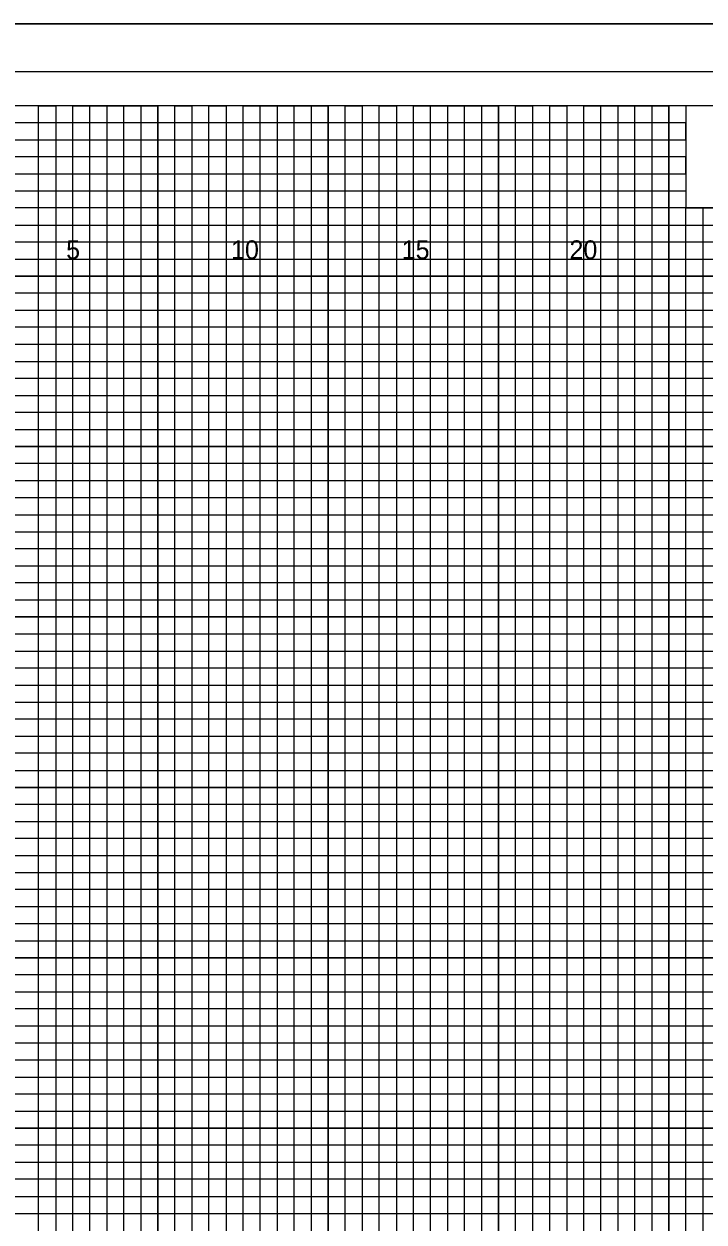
# Model space of a CAD drawing. Extents: x -4 to 103, y -2 to 209.
# Drawn here: x 54.82 to 74.78, y 103.07 to 138.22 of the extents above; entities that cross this region are included whole.
import ezdxf

# ---------------------------------------------------------------- set-up
doc = ezdxf.new("R2010")
doc.units = 0
for name, color, linetype in [('Prop XS Offset Labels', 7, 'Continuous'), ('Sheet Cross Section CELL', 7, 'Continuous'), ('Sheet Cross Section Grid Major CELL', 7, 'Continuous'), ('Sheet Cross Section Grid Middle CELL', 7, 'Continuous'), ('Sheet Cutting Line CELL', 7, 'Continuous'), ('Sheet DOT Grid CELL', 7, 'Continuous'), ('Sheet Plot Border Inside CELL', 7, 'Continuous'), ('Sheet Plot Border Outside CELL', 7, 'Continuous')]:
    doc.layers.add(name, color=color, linetype=linetype)

msp = doc.modelspace()

# ---------------------------------------------------------------- linework, layer by layer
at = {"layer": 'Sheet Cross Section CELL'}
for points in [[(102.5, 135.825), (0, 135.825), (0, 70.825), (102.5, 70.825)], [(83.75, 135.825), (74.25, 135.825), (74.25, 132.825), (83.75, 132.825)]]:
    msp.add_lwpolyline(points, close=True, dxfattribs=at)
at = {"layer": 'Sheet Cross Section Grid Major CELL'}
for points in [[(56.25, 70.825), (56.25, 135.825), (58.75, 135.825), (58.75, 70.825)], [(61.25, 70.825), (61.25, 135.825), (63.75, 135.825), (63.75, 70.825)], [(66.25, 70.825), (66.25, 135.825), (68.75, 135.825), (68.75, 70.825)], [(71.25, 70.825), (71.25, 135.825), (73.75, 135.825), (73.75, 70.825)], [(0, 133.325), (74.25, 133.325)], [(0, 128.325), (102.5, 128.325), (102.5, 130.825), (0, 130.825)], [(0, 123.325), (102.5, 123.325), (102.5, 125.825), (0, 125.825)], [(0, 118.325), (102.5, 118.325), (102.5, 120.825), (0, 120.825)], [(0, 113.325), (102.5, 113.325), (102.5, 115.825), (0, 115.825)], [(0, 108.325), (102.5, 108.325), (102.5, 110.825), (0, 110.825)], [(0, 103.325), (102.5, 103.325), (102.5, 105.825), (0, 105.825)]]:
    msp.add_lwpolyline(points, dxfattribs=at)
at = {"layer": 'Sheet Cross Section Grid Middle CELL'}
for points in [[(55.25, 70.825), (55.25, 135.825), (55.75, 135.825), (55.75, 70.825)], [(56.75, 70.825), (56.75, 135.825), (57.25, 135.825), (57.25, 70.825)], [(57.75, 70.825), (57.75, 135.825), (58.25, 135.825), (58.25, 70.825)], [(59.25, 70.825), (59.25, 135.825), (59.75, 135.825), (59.75, 70.825)], [(60.25, 70.825), (60.25, 135.825), (60.75, 135.825), (60.75, 70.825)], [(61.75, 70.825), (61.75, 135.825), (62.25, 135.825), (62.25, 70.825)], [(62.75, 70.825), (62.75, 135.825), (63.25, 135.825), (63.25, 70.825)], [(64.25, 70.825), (64.25, 135.825), (64.75, 135.825), (64.75, 70.825)], [(65.25, 70.825), (65.25, 135.825), (65.75, 135.825), (65.75, 70.825)], [(66.75, 70.825), (66.75, 135.825), (67.25, 135.825), (67.25, 70.825)], [(67.75, 70.825), (67.75, 135.825), (68.25, 135.825), (68.25, 70.825)], [(69.25, 70.825), (69.25, 135.825)], [(69.25, 135.825), (69.75, 135.825), (69.75, 70.825)], [(70.25, 70.825), (70.25, 135.825), (70.75, 135.825), (70.75, 70.825)], [(71.75, 70.825), (71.75, 135.825), (72.25, 135.825), (72.25, 70.825)], [(72.75, 70.825), (72.75, 135.825), (73.25, 135.825), (73.25, 70.825)], [(0, 132.825), (0, 133.825), (74.25, 133.825), (74.25, 134.325), (0, 134.325), (0, 134.825), (74.25, 134.825), (74.25, 135.325), (0, 135.325)], [(0, 132.325), (102.5, 132.325), (102.5, 132.825), (0, 132.825)], [(74.25, 70.825), (74.25, 132.825), (74.75, 132.825), (74.75, 70.825)], [(0, 131.325), (102.5, 131.325), (102.5, 131.825), (0, 131.825)], [(0, 129.825), (102.5, 129.825), (102.5, 130.325), (0, 130.325)], [(0, 128.825), (102.5, 128.825), (102.5, 129.325), (0, 129.325)], [(0, 127.325), (102.5, 127.325), (102.5, 127.825), (0, 127.825)], [(0, 126.325), (102.5, 126.325), (102.5, 126.825), (0, 126.825)], [(0, 124.825), (102.5, 124.825), (102.5, 125.325), (0, 125.325)], [(0, 123.825), (102.5, 123.825), (102.5, 124.325), (0, 124.325)], [(0, 122.325), (102.5, 122.325), (102.5, 122.825), (0, 122.825)], [(0, 121.325), (102.5, 121.325), (102.5, 121.825), (0, 121.825)], [(0, 119.825), (102.5, 119.825), (102.5, 120.325), (0, 120.325)], [(0, 118.825), (102.5, 118.825), (102.5, 119.325), (0, 119.325)], [(0, 117.325), (102.5, 117.325), (102.5, 117.825), (0, 117.825)], [(0, 116.325), (102.5, 116.325), (102.5, 116.825), (0, 116.825)], [(0, 114.825), (102.5, 114.825), (102.5, 115.325), (0, 115.325)], [(0, 113.825), (102.5, 113.825), (102.5, 114.325), (0, 114.325)], [(0, 112.325), (102.5, 112.325), (102.5, 112.825), (0, 112.825)], [(0, 111.325), (102.5, 111.325), (102.5, 111.825), (0, 111.825)], [(0, 109.825), (102.5, 109.825), (102.5, 110.325), (0, 110.325)], [(0, 108.825), (102.5, 108.825), (102.5, 109.325), (0, 109.325)], [(0, 107.325), (102.5, 107.325), (102.5, 107.825), (0, 107.825)], [(0, 106.325), (102.5, 106.325), (102.5, 106.825), (0, 106.825)], [(0, 104.825), (102.5, 104.825), (102.5, 105.325), (0, 105.325)], [(0, 103.825), (102.5, 103.825), (102.5, 104.325), (0, 104.325)]]:
    msp.add_lwpolyline(points, dxfattribs=at)
at = {"layer": 'Sheet Cutting Line CELL'}
msp.add_line((-3.5, 138.225), (103.4, 138.225), dxfattribs=at)
at = {"layer": 'Sheet DOT Grid CELL'}
for p, q in [((56.25, 70.825), (56.25, 135.825)), ((58.75, 70.825), (58.75, 135.825)), ((61.25, 70.825), (61.25, 135.825)), ((63.75, 70.825), (63.75, 135.825)), ((66.25, 70.825), (66.25, 135.825)), ((68.75, 70.825), (68.75, 135.825)), ((71.25, 70.825), (71.25, 135.825)), ((73.75, 70.825), (73.75, 135.825)), ((0, 133.325), (74.25, 133.325)), ((0, 130.825), (102.5, 130.825)), ((0, 128.325), (102.5, 128.325)), ((0, 125.825), (102.5, 125.825)), ((0, 123.325), (102.5, 123.325)), ((0, 120.825), (102.5, 120.825)), ((0, 118.325), (102.5, 118.325)), ((0, 115.825), (102.5, 115.825)), ((0, 113.325), (102.5, 113.325)), ((0, 110.825), (102.5, 110.825)), ((0, 108.325), (102.5, 108.325)), ((0, 105.825), (102.5, 105.825)), ((0, 103.325), (102.5, 103.325))]:
    msp.add_line(p, q, dxfattribs=at)
at = {"layer": 'Sheet Plot Border Inside CELL'}
msp.add_lwpolyline([(103, 136.825), (-2.8, 136.825), (-2.8, 69.825), (103, 69.825)], close=True, dxfattribs=at)
at = {"layer": 'Sheet Plot Border Outside CELL'}
msp.add_lwpolyline([(103.4, 138.225), (-3.5, 138.225), (-3.5, 68.4), (103.4, 68.4)], close=True, dxfattribs=at)

# ---------------------------------------------------------------- texts
at = {"layer": 'Prop XS Offset Labels'}
for s, p in [('5', (56.05742, 131.325)), ('10', (60.89708, 131.325)), ('15', (65.90575, 131.325)), ('20', (70.83125, 131.325))]:
    msp.add_text(s, height=0.55, dxfattribs=at).set_placement(p)

doc.saveas('drawing.dxf')
